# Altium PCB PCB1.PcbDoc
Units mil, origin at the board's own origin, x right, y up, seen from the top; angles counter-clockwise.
Board outline 643 x 2579 mil, 2 copper layers (Top Layer, Bottom Layer), stack 60.4 mil thick; 2 components, 80 nets, 168 pads, 0 vias.
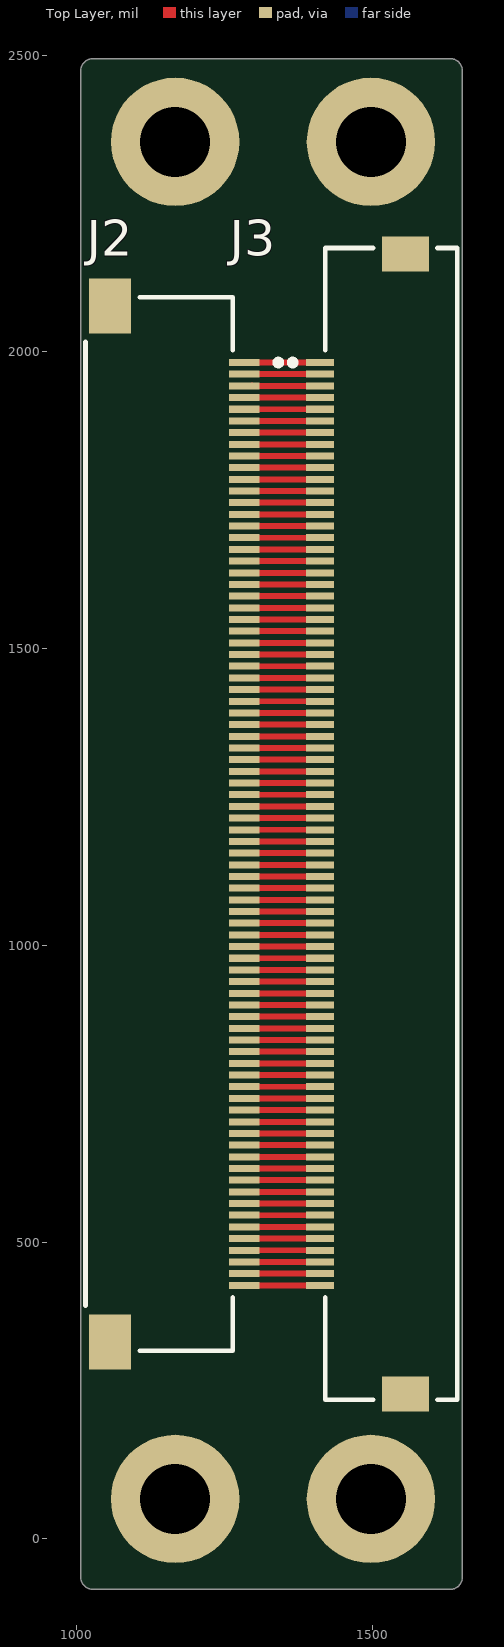
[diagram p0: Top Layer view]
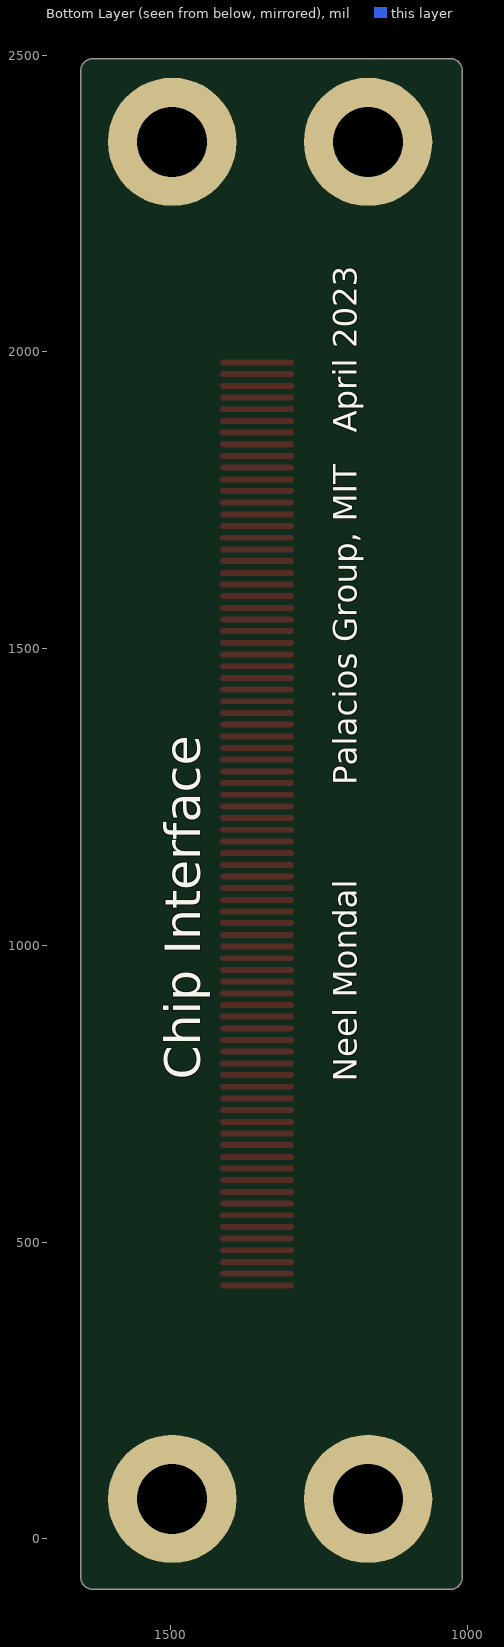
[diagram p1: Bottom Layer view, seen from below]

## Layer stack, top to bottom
Top Solder: solder mask 0.5, Solder Resist, Dk 3.3
Top Layer: signal copper 0.7
Dielectric1: core 59, FR-4, Dk 4.3
Bottom Layer: signal copper 0.7
Bottom Solder: solder mask 0.5, Solder Resist, Dk 3.3

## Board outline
1008,-65 1008,2474 cw(c1028,2474) 1028,2494 1631,2494 cw(c1631,2474) 1651,2474 1651,-65 cw(c1631,-65) 1631,-85 1028,-85 cw(c1028,-65)

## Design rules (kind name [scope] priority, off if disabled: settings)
Clearance [All] p1: gap=6 ignorepadtopadclearanceinfootprint=FALSE
DiffPairsRouting [All] p1: maxlimit=10 minlimit=10 mostfreqgap=10 toplayer_minwidth=10 toplayer_maxwidth=10 toplayer_prefwidth=10 bottomlayer_minwidth=10 bottomlayer_maxwidth=10 bottomlayer_prefwidth=10 maxuncoupledlength=500
HoleSize [All] p1: absolutevalues=TRUE maxlimit=300 minlimit=10 maxpercent=80.000 minpercent=20.000
MinimumAnnularRing [All] p1: minimumring=10
MinimumSolderMaskSliver [All] p1: minsoldermaskwidth=7
PasteMaskExpansion [All] p1: expansion=10
PlaneClearance [All] p1: clearance=15
PlaneConnect [All] p1: pad.planeconnectstyle=Relief pad.reliefexpansion=20 pad.reliefentries=4 pad.reliefconductorwidth=10 pad.reliefairgap=10 via.planeconnectstyle=Direct via.reliefexpansion=20 via.reliefentries=4 via.reliefconductorwidth=10 via.reliefairgap=10
PolygonConnect [All] p1: thpad.connectstyle=Relief thpad.reliefconductorwidth=10 thpad.reliefentries=4 thpad.polygonreliefangle="90 Angle" thpad.airgapwidth=10 smdpad.connectstyle=Relief smdpad.reliefconductorwidth=10 smdpad.reliefentries=4 smdpad.polygonreliefangle="90 Angle" smdpad.airgapwidth=10 via.connectstyle=Direct via.reliefconductorwidth=10 via.reliefentries=4 via.polygonreliefangle="90 Angle" via.airgapwidth=10
RoutingVias [All] p1: holewidth=10 width=20 viastyle="Through Hole" minholewidth=10 minwidth=20 maxholewidth=10 maxwidth=20
SMDNeckDown [All] p1: percent=100.000
SilkToSolderMaskClearance SilkscreenOverComponentPads [IsPad] p1: minsilkscreentomaskgap=10 clearancetoexposedcopper=TRUE
SolderMaskExpansion [All] p1: expansion=10 istentingtop=FALSE
Width [All] p1: maxlimit=10 minlimit=10 preferedwidth=10
23 further rules are at their usual default settings.

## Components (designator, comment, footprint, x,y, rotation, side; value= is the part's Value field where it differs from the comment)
J2 "FH28H-80S-0.5SH(05)" FP-FH28H-80S-0_5SH_05-MFG 1140,1204.63 r90 top locked
J3 "200485-0480" FP-200485-0480-MFG 1531.18,1204.63 r90 top locked

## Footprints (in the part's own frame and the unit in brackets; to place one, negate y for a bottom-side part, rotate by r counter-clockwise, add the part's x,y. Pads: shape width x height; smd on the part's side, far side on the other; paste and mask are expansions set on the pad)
FP-200485-0480-MFG [mm]
  rect 0.3x1.2 smd paste-1000 mask+0: 1(19.75,3.045) 2(19.25,3.045) 3(18.75,3.045) 4(18.25,3.045) 5(17.75,3.045) 6(17.25,3.045) 7(16.75,3.045) 8(16.25,3.045) 9(15.75,3.045) 10(15.25,3.045) 11(14.75,3.045) 12(14.25,3.045) 13(13.75,3.045) 14(13.25,3.045) 15(12.75,3.045) 16(12.25,3.045) 17(11.75,3.045) 18(11.25,3.045) 19(10.75,3.045) 20(10.25,3.045) 21(9.75,3.045) 22(9.25,3.045) 23(8.75,3.045) 24(8.25,3.045) 25(7.75,3.045) 26(7.25,3.045) 27(6.75,3.045) 28(6.25,3.045) 29(5.75,3.045) 30(5.25,3.045) 31(4.75,3.045) 32(4.25,3.045) 33(3.75,3.045) 34(3.25,3.045) 35(2.75,3.045) 36(2.25,3.045) 37(1.75,3.045) 38(1.25,3.045) 39(0.75,3.045) 40(0.25,3.045) 41(-0.25,3.045) 42(-0.75,3.045) 43(-1.25,3.045) 44(-1.75,3.045) 45(-2.25,3.045) 46(-2.75,3.045) 47(-3.25,3.045) 48(-3.75,3.045) 49(-4.25,3.045) 50(-4.75,3.045) 51(-5.25,3.045) 52(-5.75,3.045) 53(-6.25,3.045) 54(-6.75,3.045) 55(-7.25,3.045) 56(-7.75,3.045) 57(-8.25,3.045) 58(-8.75,3.045) 59(-9.25,3.045) 60(-9.75,3.045) 61(-10.25,3.045) 62(-10.75,3.045) 63(-11.25,3.045) 64(-11.75,3.045) 65(-12.25,3.045) 66(-12.75,3.045) 67(-13.25,3.045) 68(-13.75,3.045) 69(-14.25,3.045) 70(-14.75,3.045) 71(-15.25,3.045) 72(-15.75,3.045) 73(-16.25,3.045) 74(-16.75,3.045) 75(-17.25,3.045) 76(-17.75,3.045) 77(-18.25,3.045) 78(-18.75,3.045) 79(-19.25,3.045) 80(-19.75,3.045)
  rect 1.5x2 smd paste+0 mask+0: 81(-24.4,-0.605) 82(24.4,-0.605)
  silkscreen extent -24.65,-2.82 24.65,4.34, body extent -25.25,-2.93 25.25,3.74, height 0.25
FP-FH28H-80S-0_5SH_05-MFG [mm]
  rect 0.3x1.3 smd paste-1000 mask+0: 1(19.75,-3.65) 2(19.25,-3.65) 3(18.75,-3.65) 4(18.25,-3.65) 5(17.75,-3.65) 6(17.25,-3.65) 7(16.75,-3.65) 8(16.25,-3.65) 9(15.75,-3.65) 10(15.25,-3.65) 11(14.75,-3.65) 12(14.25,-3.65) 13(13.75,-3.65) 14(13.25,-3.65) 15(12.75,-3.65) 16(12.25,-3.65) 17(11.75,-3.65) 18(11.25,-3.65) 19(10.75,-3.65) 20(10.25,-3.65) 21(9.75,-3.65) 22(9.25,-3.65) 23(8.75,-3.65) 24(8.25,-3.65) 25(7.75,-3.65) 26(7.25,-3.65) 27(6.75,-3.65) 28(6.25,-3.65) 29(5.75,-3.65) 30(5.25,-3.65) 31(4.75,-3.65) 32(4.25,-3.65) 33(3.75,-3.65) 34(3.25,-3.65) 35(2.75,-3.65) 36(2.25,-3.65) 37(1.75,-3.65) 38(1.25,-3.65) 39(0.75,-3.65) 40(0.25,-3.65) 41(-0.25,-3.65) 42(-0.75,-3.65) 43(-1.25,-3.65) 44(-1.75,-3.65) 45(-2.25,-3.65) 46(-2.75,-3.65) 47(-3.25,-3.65) 48(-3.75,-3.65) 49(-4.25,-3.65) 50(-4.75,-3.65) 51(-5.25,-3.65) 52(-5.75,-3.65) 53(-6.25,-3.65) 54(-6.75,-3.65) 55(-7.25,-3.65) 56(-7.75,-3.65) 57(-8.25,-3.65) 58(-8.75,-3.65) 59(-9.25,-3.65) 60(-9.75,-3.65) 61(-10.25,-3.65) 62(-10.75,-3.65) 63(-11.25,-3.65) 64(-11.75,-3.65) 65(-12.25,-3.65) 66(-12.75,-3.65) 67(-13.25,-3.65) 68(-13.75,-3.65) 69(-14.25,-3.65) 70(-14.75,-3.65) 71(-15.25,-3.65) 72(-15.75,-3.65) 73(-16.25,-3.65) 74(-16.75,-3.65) 75(-17.25,-3.65) 76(-17.75,-3.65) 77(-18.25,-3.65) 78(-18.75,-3.65) 79(-19.25,-3.65) 80(-19.75,-3.65)
  rect 2.35x1.8 smd paste+0 mask+0: 81(-22.175,2.1) 82(22.175,2.1)
  silkscreen extent -22.55,-5.23 22.55,3.15, body extent -23.45,-4.4 23.45,3.25, height 0.25

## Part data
J2: library part CMP-11609-000031-1, "CONN FFC BOTTOM 80POS 0.50MM R/A", Contact Resistance=50mR, Current Rating=500mA, Flammability Rating="UL94 V-0", Housing Color=Grey, Insulation Resistance=500MR, Max Operating Temperature=85°C, Max Voltage Rating (AC)=50V, Min Operating Temperature=-40°C, Package Quantity=1
J3: library part CMP-04775-000024-1, "0.5 ONE-TOUCH RA 80P"

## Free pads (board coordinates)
  round 216.54 hole 118.11: 4(1167,67) 4(1167,2354) 4(1497,67) 4(1497,2354)

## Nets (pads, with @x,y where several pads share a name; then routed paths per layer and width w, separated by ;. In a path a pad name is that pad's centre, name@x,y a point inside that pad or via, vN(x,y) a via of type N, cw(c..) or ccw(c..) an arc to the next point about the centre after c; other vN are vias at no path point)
NetJ2_1: J2.1 J3.1 | length 115.4
  Top Layer w10: J2.1@1296.38,1982.19 J3.1 J3.1@1411.13,1982.36 ; J2.1@1296.38,1982.53 J2.1@1296.55,1982.36
NetJ2_2: J2.2 J3.2 | length 115.2
  Top Layer w10: J2.2@1296.38,1962.5 J3.2 ; J2.2@1296.38,1962.84 J2.2@1296.55,1962.67
NetJ2_3: J2.3 J3.3 | length 115.6
  Top Layer w10: J2.3@1296.04,1942.82 1296.21,1942.99 J2.3@1296.38,1943.16 ; J2.3@1296.38,1942.82 J3.3 J3.3@1411.13,1942.99
NetJ2_4: J2.4 J3.4 | length 115.4
  Top Layer w10: J2.4@1296.38,1923.13 J3.4 J3.4@1411.13,1923.3 ; J2.4@1296.38,1923.47 J2.4@1296.55,1923.3
NetJ2_5: J2.5 J3.5 | length 115.4
  Top Layer w10: J2.5@1296.38,1903.45 J3.5 J3.5@1411.13,1903.62 ; J2.5@1296.38,1903.79 J2.5@1296.55,1903.62
NetJ2_6: J2.6 J3.6 | length 115.4
  Top Layer w10: J2.6@1296.38,1883.76 J3.6 J3.6@1411.13,1883.93 ; J2.6@1296.38,1884.1 J2.6@1296.55,1883.93
NetJ2_7: J2.7 J3.7 | length 115.4
  Top Layer w10: J2.7@1296.38,1864.08 J3.7 J3.7@1411.13,1864.25 ; J2.7@1296.38,1864.42 J2.7@1296.55,1864.25
NetJ2_8: J2.8 J3.8 | length 115.4
  Top Layer w10: J2.8@1296.38,1844.39 J3.8 J3.8@1411.13,1844.56 ; J2.8@1296.38,1844.73 J2.8@1296.55,1844.56
NetJ2_9: J2.9 J3.9 | length 115.4
  Top Layer w10: J2.9@1296.38,1824.71 J3.9 J3.9@1411.13,1824.88 ; J2.9@1296.38,1825.05 J2.9@1296.55,1824.88
NetJ2_10: J2.10 J3.10 | length 115.4
  Top Layer w10: J2.10@1296.38,1805.02 J3.10 J3.10@1411.13,1805.19 ; J2.10@1296.38,1805.36 J2.10@1296.55,1805.19
NetJ2_11: J2.11 J3.11 | length 114.9
  Top Layer w10: J2.11@1296.38,1785.34 J3.11
NetJ2_12: J2.12 J3.12 | length 114.9
  Top Layer w10: J2.12@1296.38,1765.65 J3.12
NetJ2_13: J2.13 J3.13 | length 114.9
  Top Layer w10: J2.13@1296.38,1745.97 J3.13
NetJ2_14: J2.14 J3.14 | length 114.9
  Top Layer w10: J2.14@1296.38,1726.28 J3.14
NetJ2_15: J2.15 J3.15 | length 114.9
  Top Layer w10: J2.15@1296.38,1706.6 J3.15
NetJ2_16: J2.16 J3.16 | length 114.9
  Top Layer w10: J2.16@1296.38,1686.91 J3.16
NetJ2_17: J2.17 J3.17 | length 114.9
  Top Layer w10: J2.17@1296.38,1667.23 J3.17
NetJ2_18: J2.18 J3.18 | length 114.9
  Top Layer w10: J2.18@1296.38,1647.54 J3.18
NetJ2_19: J2.19 J3.19 | length 114.9
  Top Layer w10: J2.19@1296.38,1627.86 J3.19
NetJ2_20: J2.20 J3.20 | length 114.9
  Top Layer w10: J2.20@1296.38,1608.17 J3.20
NetJ2_21: J2.21 J3.21 | length 114.9
  Top Layer w10: J2.21@1296.38,1588.49 J3.21
NetJ2_22: J2.22 J3.22 | length 114.9
  Top Layer w10: J2.22@1296.38,1568.8 J3.22
NetJ2_23: J2.23 J3.23 | length 114.9
  Top Layer w10: J2.23@1296.38,1549.12 J3.23
NetJ2_24: J2.24 J3.24 | length 114.9
  Top Layer w10: J2.24@1296.38,1529.43 J3.24
NetJ2_25: J2.25 J3.25 | length 114.9
  Top Layer w10: J2.25@1296.38,1509.75 J3.25
NetJ2_26: J2.26 J3.26 | length 114.9
  Top Layer w10: J2.26@1296.38,1490.06 J3.26
NetJ2_27: J2.27 J3.27 | length 114.9
  Top Layer w10: J2.27@1296.38,1470.38 J3.27
NetJ2_28: J2.28 J3.28 | length 114.9
  Top Layer w10: J2.28@1296.38,1450.69 J3.28
NetJ2_29: J2.29 J3.29 | length 114.9
  Top Layer w10: J2.29@1296.38,1431.01 J3.29
NetJ2_30: J2.30 J3.30 | length 114.9
  Top Layer w10: J2.30@1296.38,1411.32 J3.30
NetJ2_31: J2.31 J3.31 | length 114.9
  Top Layer w10: J2.31@1296.38,1391.64 J3.31
NetJ2_32: J2.32 J3.32 | length 114.9
  Top Layer w10: J2.32@1296.38,1371.95 J3.32
NetJ2_33: J2.33 J3.33 | length 114.9
  Top Layer w10: J2.33@1296.38,1352.27 J3.33
NetJ2_34: J2.34 J3.34 | length 114.9
  Top Layer w10: J2.34@1296.38,1332.58 J3.34
NetJ2_35: J2.35 J3.35 | length 114.9
  Top Layer w10: J2.35@1296.38,1312.9 J3.35
NetJ2_36: J2.36 J3.36 | length 114.9
  Top Layer w10: J2.36@1296.38,1293.21 J3.36
NetJ2_37: J2.37 J3.37 | length 114.9
  Top Layer w10: J2.37@1296.38,1273.53 J3.37
NetJ2_38: J2.38 J3.38 | length 114.9
  Top Layer w10: J2.38@1296.38,1253.84 J3.38
NetJ2_39: J2.39 J3.39 | length 114.9
  Top Layer w10: J2.39@1296.38,1234.16 J3.39
NetJ2_40: J2.40 J3.40 | length 114.9
  Top Layer w10: J2.40@1296.38,1214.47 J3.40
NetJ2_41: J2.41 J3.41 | length 114.9
  Top Layer w10: J2.41@1296.38,1194.79 J3.41
NetJ2_42: J2.42 J3.42 | length 114.9
  Top Layer w10: J2.42@1296.38,1175.1 J3.42
NetJ2_43: J2.43 J3.43 | length 114.9
  Top Layer w10: J2.43@1296.38,1155.42 J3.43
NetJ2_44: J2.44 J3.44 | length 114.9
  Top Layer w10: J2.44@1296.38,1135.73 J3.44
NetJ2_45: J2.45 J3.45 | length 114.9
  Top Layer w10: J2.45@1296.38,1116.05 J3.45
NetJ2_46: J2.46 J3.46 | length 114.9
  Top Layer w10: J2.46@1296.38,1096.36 J3.46
NetJ2_47: J2.47 J3.47 | length 114.9
  Top Layer w10: J2.47@1296.38,1076.68 J3.47
NetJ2_48: J2.48 J3.48 | length 114.9
  Top Layer w10: J2.48@1296.38,1056.99 J3.48
NetJ2_49: J2.49 J3.49 | length 114.9
  Top Layer w10: J2.49@1296.38,1037.31 J3.49
NetJ2_50: J2.50 J3.50 | length 114.9
  Top Layer w10: J2.50@1296.38,1017.62 J3.50
NetJ2_51: J2.51 J3.51 | length 114.9
  Top Layer w10: J2.51@1296.38,997.94 J3.51
NetJ2_52: J2.52 J3.52 | length 114.9
  Top Layer w10: J2.52@1296.38,978.25 J3.52
NetJ2_53: J2.53 J3.53 | length 114.9
  Top Layer w10: J2.53@1296.38,958.57 J3.53
NetJ2_54: J2.54 J3.54 | length 114.9
  Top Layer w10: J2.54@1296.38,938.88 J3.54
NetJ2_55: J2.55 J3.55 | length 114.9
  Top Layer w10: J2.55@1296.38,919.2 J3.55
NetJ2_56: J2.56 J3.56 | length 114.9
  Top Layer w10: J2.56@1296.38,899.51 J3.56
NetJ2_57: J2.57 J3.57 | length 114.9
  Top Layer w10: J2.57@1296.38,879.83 J3.57
NetJ2_58: J2.58 J3.58 | length 114.9
  Top Layer w10: J2.58@1296.38,860.14 J3.58
NetJ2_59: J2.59 J3.59 | length 114.9
  Top Layer w10: J2.59@1296.38,840.46 J3.59
NetJ2_60: J2.60 J3.60 | length 114.9
  Top Layer w10: J2.60@1296.38,820.77 J3.60
NetJ2_61: J2.61 J3.61 | length 114.9
  Top Layer w10: J2.61@1296.38,801.09 J3.61
NetJ2_62: J2.62 J3.62 | length 114.9
  Top Layer w10: J2.62@1296.38,781.4 J3.62
NetJ2_63: J2.63 J3.63 | length 114.9
  Top Layer w10: J2.63@1296.38,761.72 J3.63
NetJ2_64: J2.64 J3.64 | length 114.9
  Top Layer w10: J2.64@1296.38,742.03 J3.64
NetJ2_65: J2.65 J3.65 | length 114.9
  Top Layer w10: J2.65@1296.38,722.35 J3.65
NetJ2_66: J2.66 J3.66 | length 114.9
  Top Layer w10: J2.66@1296.38,702.66 J3.66
NetJ2_67: J2.67 J3.67 | length 114.9
  Top Layer w10: J2.67@1296.38,682.98 J3.67
NetJ2_68: J2.68 J3.68 | length 114.9
  Top Layer w10: J2.68@1296.38,663.29 J3.68
NetJ2_69: J2.69 J3.69 | length 114.9
  Top Layer w10: J2.69@1296.38,643.61 J3.69
NetJ2_70: J2.70 J3.70 | length 114.9
  Top Layer w10: J2.70@1296.38,623.92 J3.70
NetJ2_71: J2.71 J3.71 | length 114.9
  Top Layer w10: J2.71@1296.38,604.24 J3.71
NetJ2_72: J2.72 J3.72 | length 114.9
  Top Layer w10: J2.72@1296.38,584.55 J3.72
NetJ2_73: J2.73 J3.73 | length 114.9
  Top Layer w10: J2.73@1296.38,564.87 J3.73
NetJ2_74: J2.74 J3.74 | length 114.9
  Top Layer w10: J2.74@1296.38,545.18 J3.74
NetJ2_75: J2.75 J3.75 | length 114.9
  Top Layer w10: J2.75@1296.38,525.5 J3.75
NetJ2_76: J2.76 J3.76 | length 114.9
  Top Layer w10: J2.76@1296.38,505.81 J3.76
NetJ2_77: J2.77 J3.77 | length 114.9
  Top Layer w10: J2.77@1296.38,486.13 J3.77
NetJ2_78: J2.78 J3.78 | length 114.9
  Top Layer w10: J2.78@1296.38,466.44 J3.78
NetJ2_79: J2.79 J3.79 | length 114.9
  Top Layer w10: J2.79@1296.38,446.76 J3.79
NetJ2_80: J2.80 J3.80 | length 114.9
  Top Layer w10: J2.80@1296.38,427.07 J3.80
pads on no net: J2.81 J2.82 J3.81 J3.82

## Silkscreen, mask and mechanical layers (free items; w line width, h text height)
Bottom Overlay:
  text "Chip Interface" at 1449.38,773.63 h60 r270
  text "Neel Mondal         Palacios Group, MIT   April 2023" at 1186.34,770.52 h40 r270
Board:
  the board outline again, w5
